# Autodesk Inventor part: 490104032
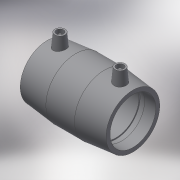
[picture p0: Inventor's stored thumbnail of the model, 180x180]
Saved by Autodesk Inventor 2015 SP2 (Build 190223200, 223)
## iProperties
Created: 2017-06
Part Number: 490104032
Material: Generic
Description: PLASSON COUPLER 32-32
Document SubType Name: Modeling
Designer: KIM
Mass: 60.7693 g
Surface Area: 251.171 cm^2
Volume: 60.7693 cm^3
Density: 1 g/cm^3
Appearance: Default
Author: KIM
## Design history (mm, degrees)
derived "490104.ipt"
feature "Solid1::490104.ipt"
tag "TaggingFeature1"
body "Solid1"
other parameters: "d0" = 88, "d1" = 32, "d2" = 44, "d3" = 42, "d4" = 29.33333, "d5" = 39.6, "d6" = 30.4, "d7" = 32, "d8" = 168 deg, "d10" = 16.8, "d11" = 5.6, "d13" = 88, "d14" = 17.6296, "d15" = 42, "d16" = 42, "d17" = 30.4, "d18" = 32, "d19" = 3.52592, "d20" = 168 deg, "d22" = 41.36, "d23" = 44, "d24" = 40.1192, "d25" = 135 deg, "d26" = 35.2, "d27" = 135 deg, "d29" = 42, "d30" = 14, "d31" = 30.8, "d34" = 5 deg, "d35" = 15, "d39" = 5 deg, "d41" = 4, "d42" = 14, "d43" = 0, "d45" = 4, "d46" = 14, "d47" = 0, "d48" = 3, "d49" = 0, "d50" = 3, "d51" = 0, "d52" = 12.18, "d53" = 3.045, "d_" = 32, "L_" = 88, "L_1" = 42, "D_" = 44, "A_" = 42, "d_2" = 12
